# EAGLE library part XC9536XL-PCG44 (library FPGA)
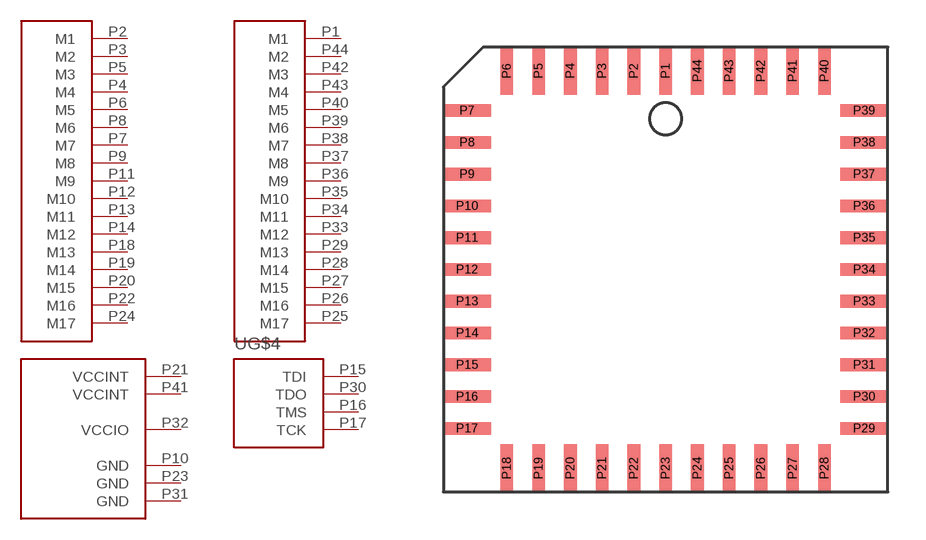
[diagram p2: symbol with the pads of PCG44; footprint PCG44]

Designator prefix -; gates F1=XC9536XL-PCG44-FUNCTIONBLOCK F2=XC9536XL-PCG44-FUNCTIONBLOCK G$4=XC9536XL-PCG44-CONF G$1=XC9536XL-PCG44-PWR

## XC9536XL-PCG44  [PCG44]
P1  F2:M1
P2  F1:M1
P3  F1:M2
P4  F1:M4
P5  F1:M3
P6  F1:M5
P7  F1:M7
P8  F1:M6
P9  F1:M8
P10  G$1:GND
P11  F1:M9
P12  F1:M10
P13  F1:M11
P14  F1:M12
P15  G$4:TDI  in
P16  G$4:TMS  in
P17  G$4:TCK  in
P18  F1:M13
P19  F1:M14
P20  F1:M15
P21  G$1:VCCINT  pwr
P22  F1:M16
P23  G$1:GND
P24  F1:M17
P25  F2:M17
P26  F2:M16
P27  F2:M15
P28  F2:M14
P29  F2:M13
P30  G$4:TDO  out
P31  G$1:GND
P32  G$1:VCCIO  pwr
P33  F2:M12
P34  F2:M11
P35  F2:M10
P36  F2:M9
P37  F2:M8
P38  F2:M7
P39  F2:M6
P40  F2:M5
P41  G$1:VCCINT  pwr
P42  F2:M3
P43  F2:M4
P44  F2:M2

## Footprint PCG44 (pad centres in mm)
smd 0.508 x 1.905: P1 0,7.938; P2 -1.27,7.938; P3 -2.54,7.938; P4 -3.81,7.938; P5 -5.08,7.938; P6 -6.35,7.938; P18 -6.35,-7.938; P19 -5.08,-7.938; P20 -3.81,-7.938; P21 -2.54,-7.938; P22 -1.27,-7.938; P23 0,-7.938; P24 1.27,-7.938; P25 2.54,-7.938; P26 3.81,-7.938; P27 5.08,-7.938; P28 6.35,-7.938; P40 6.35,7.938; P41 5.08,7.938; P42 3.81,7.938; P43 2.54,7.938; P44 1.27,7.938
smd 1.905 x 0.508: P7 -7.938,6.35; P8 -7.938,5.08; P9 -7.938,3.81; P10 -7.938,2.54; P11 -7.938,1.27; P12 -7.938,0; P13 -7.938,-1.27; P14 -7.938,-2.54; P15 -7.938,-3.81; P16 -7.938,-5.08; P17 -7.938,-6.35; P29 7.938,-6.35; P30 7.938,-5.08; P31 7.938,-3.81; P32 7.938,-2.54; P33 7.938,-1.27; P34 7.938,0; P35 7.938,1.27; P36 7.938,2.54; P37 7.938,3.81; P38 7.938,5.08; P39 7.938,6.35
